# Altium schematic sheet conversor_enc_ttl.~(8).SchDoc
size A4
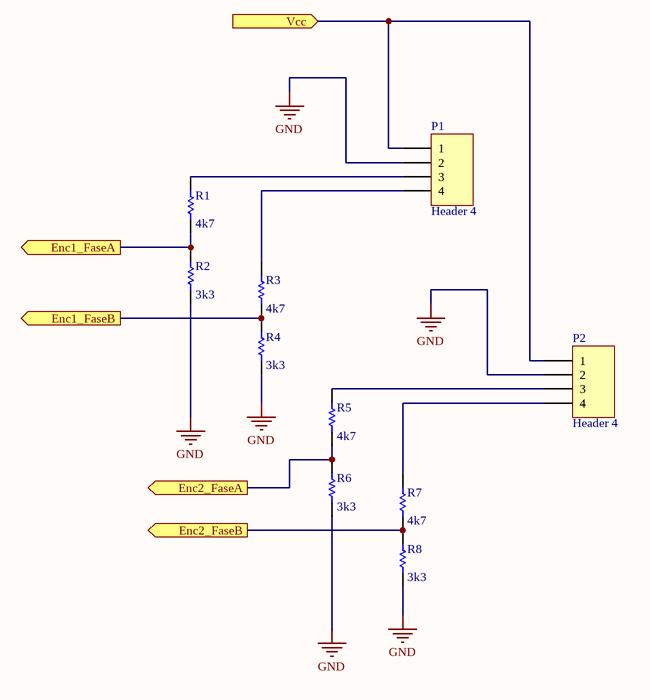
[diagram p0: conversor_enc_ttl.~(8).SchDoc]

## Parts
P1  Header 4  [HDR1X4]
P2  Header 4  [HDR1X4]
R1  value 4k7  [1005[0402]]  (hidden comment: metal film 2%)
R2  value 3k3  [1005[0402]]  (hidden comment: metal film 2%)
R3  value 4k7  [1005[0402]]  (hidden comment: metal film 2%)
R4  value 3k3  [1005[0402]]  (hidden comment: metal film 2%)
R5  value 4k7  [1005[0402]]  (hidden comment: metal film 2%)
R6  value 3k3  [1005[0402]]  (hidden comment: metal film 2%)
R7  value 4k7  [1005[0402]]  (hidden comment: metal film 2%)
R8  value 3k3  [1005[0402]]  (hidden comment: metal film 2%)

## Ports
Enc1_FaseA (out), Enc1_FaseB (out), Enc2_FaseA (out), Enc2_FaseB (out), Vcc (in)

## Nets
GND: P1.2 P2.2 R2.1 R4.1 R6.1 R8.1
Enc1_FaseA: R1.1 R2.2 ; port Enc1_FaseA
Enc1_FaseB: R3.1 R4.2 ; port Enc1_FaseB
Enc2_FaseA: R5.1 R6.2 ; port Enc2_FaseA
Enc2_FaseB: R7.1 R8.2 ; port Enc2_FaseB
Vcc: P1.1 P2.1 ; port Vcc
NetP1_3: P1.3 R1.2
NetP1_4: P1.4 R3.2
NetP2_3: P2.3 R5.2
NetP2_4: P2.4 R7.2

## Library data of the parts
P1 P2 = Header 4: Header, 4-Pin
R1-R8 = Res Semi: Semiconductor Resistor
